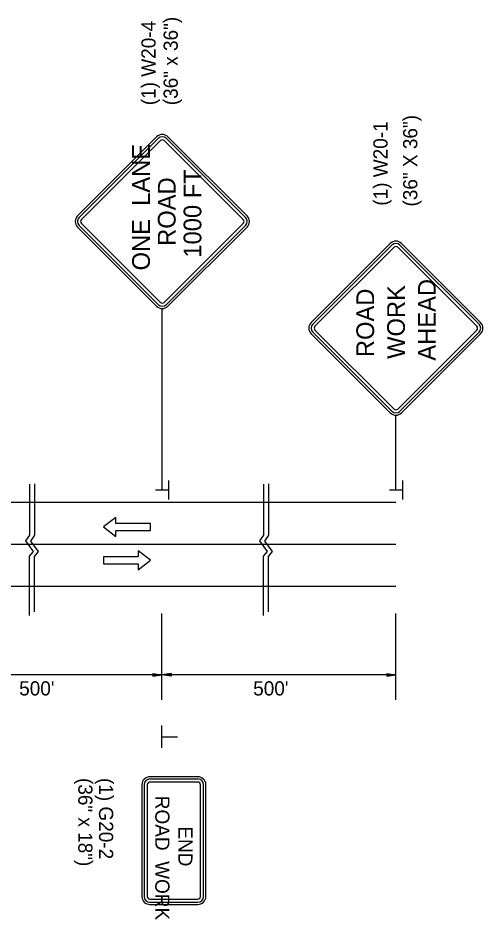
# Model space of a CAD drawing. Extents: x 1926586 to 1930787, y 596452 to 599566.
# Drawn here: x 1928179.6 to 1928376.1, y 598779.1 to 599160.5 of the extents above; entities that cross this region are included whole.
import ezdxf

# ---------------------------------------------------------------- set-up
doc = ezdxf.new("R2010")
doc.units = 0
for name, color, linetype in [('Default', 7, 'Continuous'), ('P_TC_Signs_Temporary', 7, 'Continuous'), ('R_Border', 7, 'Continuous'), ('R_Striping', 7, 'Continuous')]:
    doc.layers.add(name, color=color, linetype=linetype)

msp = doc.modelspace()

# ---------------------------------------------------------------- linework, layer by layer
at = {"layer": 'Default'}
for p, q in [((1928243.29, 598964.87), (1928243.29, 598956.86)), ((1928342.19, 598964.87), (1928342.19, 598956.86)), ((1928243.18, 598960.89), (1928237.71, 598960.89)), ((1928342.08, 598960.89), (1928336.61, 598960.89)), ((1927909.48, 598955.79), (1928339.34, 598955.76)), ((1927909.48, 598938), (1928339.34, 598937.97)), ((1927909.48, 598920.21), (1928339.34, 598920.18)), ((1928240.44, 598872.15), (1928240.44, 598908.73)), ((1928339.34, 598872.15), (1928339.34, 598908.73)), ((1928240.44, 598882.74), (1928140.69, 598882.74)), ((1928236.61, 598883.31), (1928240.44, 598882.74)), ((1928236.61, 598883.31), (1928236.61, 598882.16)), ((1928236.61, 598883.22), (1928239.8, 598882.74)), ((1928236.61, 598883.12), (1928239.14, 598882.74)), ((1928236.61, 598883.02), (1928238.5, 598882.74)), ((1928236.61, 598882.92), (1928237.85, 598882.74)), ((1928236.61, 598882.83), (1928237.21, 598882.74)), ((1928236.61, 598882.16), (1928240.44, 598882.74)), ((1928236.61, 598882.55), (1928237.85, 598882.74)), ((1928236.61, 598882.35), (1928239.14, 598882.74)), ((1928236.61, 598882.26), (1928239.8, 598882.74)), ((1928236.61, 598882.45), (1928238.5, 598882.74)), ((1928236.61, 598882.65), (1928237.21, 598882.74)), ((1928339.34, 598882.74), (1928239.59, 598882.74)), ((1928244.29, 598883.31), (1928240.46, 598882.74)), ((1928244.29, 598882.16), (1928240.46, 598882.74)), ((1928244.29, 598883.22), (1928241.1, 598882.74)), ((1928244.29, 598882.26), (1928241.1, 598882.74)), ((1928244.29, 598883.12), (1928241.76, 598882.74)), ((1928244.29, 598882.35), (1928241.76, 598882.74)), ((1928244.29, 598883.02), (1928242.4, 598882.74)), ((1928244.29, 598882.45), (1928242.4, 598882.74)), ((1928244.29, 598882.92), (1928243.05, 598882.74)), ((1928244.29, 598882.55), (1928243.05, 598882.74)), ((1928244.29, 598882.83), (1928243.69, 598882.74)), ((1928244.29, 598882.65), (1928243.69, 598882.74)), ((1928244.29, 598883.31), (1928244.29, 598882.16)), ((1928335.51, 598883.31), (1928339.34, 598882.74)), ((1928335.51, 598883.31), (1928335.51, 598882.16)), ((1928335.51, 598883.22), (1928338.7, 598882.74)), ((1928335.51, 598883.12), (1928338.04, 598882.74)), ((1928335.51, 598883.02), (1928337.4, 598882.74)), ((1928335.51, 598882.92), (1928336.75, 598882.74)), ((1928335.51, 598882.83), (1928336.11, 598882.74)), ((1928335.51, 598882.16), (1928339.34, 598882.74)), ((1928335.51, 598882.55), (1928336.75, 598882.74)), ((1928335.51, 598882.35), (1928338.04, 598882.74)), ((1928335.51, 598882.26), (1928338.7, 598882.74)), ((1928335.51, 598882.45), (1928337.4, 598882.74)), ((1928335.51, 598882.65), (1928336.11, 598882.74)), ((1928240.44, 598851.83), (1928240.44, 598861.32)), ((1928240.58, 598856.55), (1928247.06, 598856.55))]:
    msp.add_line(p, q, dxfattribs=at)
for points in [[(1928184.51, 598963.37), (1928184.51, 598941.85), (1928182.85, 598939.38), (1928186.09, 598934.95), (1928184.39, 598932.9), (1928184.38, 598907.87)], [(1928186.56, 598963.57), (1928186.56, 598941.76), (1928184.9, 598939.29), (1928188.13, 598934.86), (1928186.43, 598932.81), (1928186.43, 598909.31)], [(1928283.41, 598963.37), (1928283.41, 598941.85), (1928281.75, 598939.38), (1928284.99, 598934.95), (1928283.29, 598932.9), (1928283.28, 598907.87)], [(1928285.46, 598963.57), (1928285.46, 598941.76), (1928283.8, 598939.29), (1928287.03, 598934.86), (1928285.33, 598932.81), (1928285.33, 598909.31)]]:
    msp.add_lwpolyline(points, dxfattribs=at)
at = {"layer": 'P_TC_Signs_Temporary'}
for p, q in [((1928204.82, 599076.83), (1928238.23, 599110.24)), ((1928205.48, 599076.17), (1928238.89, 599109.58)), ((1928242.34, 599109.58), (1928275.75, 599076.17)), ((1928243, 599110.24), (1928276.41, 599076.83)), ((1928206.41, 599075.24), (1928239.82, 599108.65)), ((1928241.41, 599108.65), (1928274.82, 599075.24)), ((1928238.23, 599038.65), (1928204.82, 599072.06)), ((1928238.89, 599039.31), (1928205.48, 599072.72)), ((1928239.82, 599040.24), (1928206.41, 599073.65)), ((1928274.82, 599073.65), (1928241.41, 599040.24)), ((1928275.75, 599072.72), (1928242.34, 599039.31)), ((1928276.41, 599072.06), (1928243, 599038.65)), ((1928303.55, 599031.72), (1928336.96, 599065.13)), ((1928304.21, 599031.05), (1928337.62, 599064.47)), ((1928305.14, 599030.13), (1928338.55, 599063.54)), ((1928340.14, 599063.54), (1928373.55, 599030.13)), ((1928341.07, 599064.47), (1928374.48, 599031.05)), ((1928341.73, 599065.13), (1928375.14, 599031.72)), ((1928336.96, 598993.53), (1928303.55, 599026.94)), ((1928337.62, 598994.2), (1928304.21, 599027.61)), ((1928338.55, 598995.12), (1928305.14, 599028.54)), ((1928373.55, 599028.54), (1928340.14, 598995.12)), ((1928374.48, 599027.61), (1928341.07, 598994.2)), ((1928375.14, 599026.94), (1928341.73, 598993.53)), ((1928255.64, 598839.63), (1928235.39, 598839.63)), ((1928255.64, 598838.69), (1928235.39, 598838.69)), ((1928232.01, 598836.26), (1928232.01, 598789.01)), ((1928232.95, 598836.26), (1928232.95, 598789.01)), ((1928234.26, 598836.26), (1928234.26, 598789.01)), ((1928255.64, 598837.38), (1928235.39, 598837.38)), ((1928256.76, 598789.01), (1928256.76, 598836.26)), ((1928258.08, 598789.01), (1928258.08, 598836.26)), ((1928259.01, 598789.01), (1928259.01, 598836.26)), ((1928235.39, 598787.88), (1928255.64, 598787.88)), ((1928235.39, 598786.57), (1928255.64, 598786.57)), ((1928235.39, 598785.63), (1928255.64, 598785.63))]:
    msp.add_line(p, q, dxfattribs=at)
for centre, radius, start, end in [((1928240.62, 599107.85), 3.38, 45, 135), ((1928240.62, 599107.85), 2.44, 45, 135), ((1928240.62, 599107.85), 1.13, 45, 135), ((1928207.21, 599074.44), 3.38, 135, 225), ((1928207.21, 599074.44), 2.44, 135, 225), ((1928207.21, 599074.44), 1.13, 135, 225), ((1928274.03, 599074.44), 1.13, 315, 45), ((1928274.03, 599074.44), 2.44, 315, 45), ((1928274.03, 599074.44), 3.38, 315, 45), ((1928339.34, 599062.74), 3.38, 45, 135), ((1928339.34, 599062.74), 2.44, 45, 135), ((1928339.34, 599062.74), 1.13, 45, 135), ((1928240.62, 599041.03), 3.38, 225, 315), ((1928240.62, 599041.03), 2.44, 225, 315), ((1928240.62, 599041.03), 1.13, 225, 315), ((1928305.93, 599029.33), 3.38, 135, 225), ((1928305.93, 599029.33), 2.44, 135, 225), ((1928305.93, 599029.33), 1.13, 135, 225), ((1928372.75, 599029.33), 1.13, 315, 45), ((1928372.75, 599029.33), 2.44, 315, 45), ((1928372.75, 599029.33), 3.38, 315, 45), ((1928339.34, 598995.92), 1.13, 225, 315), ((1928339.34, 598995.92), 3.38, 225, 315), ((1928339.34, 598995.92), 2.44, 225, 315), ((1928235.39, 598836.26), 3.37, 90, 180), ((1928235.39, 598836.26), 2.44, 90, 180), ((1928255.64, 598836.26), 3.37, 360, 90), ((1928255.64, 598836.26), 2.44, 360, 90), ((1928235.39, 598836.26), 1.13, 90, 180), ((1928255.64, 598836.26), 1.13, 360, 90), ((1928235.39, 598789.01), 3.37, 180, 270), ((1928235.39, 598789.01), 2.44, 180, 270), ((1928235.39, 598789.01), 1.13, 180, 270), ((1928255.64, 598789.01), 2.44, 270, 360), ((1928255.64, 598789.01), 1.13, 270, 360), ((1928255.64, 598789.01), 3.37, 270, 360)]:
    msp.add_arc(centre, radius, start, end, dxfattribs=at)
at = {"layer": 'R_Border'}
for p, q in [((1928240.62, 598960.89), (1928240.62, 599037.66)), ((1928339.34, 598960.89), (1928339.34, 598992.54))]:
    msp.add_line(p, q, dxfattribs=at)
at = {"layer": 'R_Striping'}
for points in [[(1928220.95, 598949.3), (1928215.76, 598945.3), (1928220.95, 598941.3), (1928220.95, 598943.8), (1928235.67, 598943.8), (1928235.67, 598946.8), (1928220.95, 598946.8)], [(1928230.47, 598927.16), (1928235.67, 598931.16), (1928230.47, 598935.16), (1928230.47, 598932.66), (1928215.76, 598932.66), (1928215.76, 598929.66), (1928230.47, 598929.66)]]:
    msp.add_lwpolyline(points, close=True, dxfattribs=at)

# ---------------------------------------------------------------- texts
at = {"layer": 'Default'}
for s, rotation, p in [('(36" X 36")', 90, (1928348.39, 599080.78)), ('(1) W20-1', 90, (1928335.81, 599081.12)), ("500'", 359.9922, (1928180.12, 598874.01)), ("500'", 359.9922, (1928279.02, 598874.01))]:
    msp.add_text(s, height=6, rotation=rotation, dxfattribs=at).set_placement(p)
at = {"layer": 'P_TC_Signs_Temporary'}
for s, height, rotation, p in [('ONE  LANE', 7.5, 90, (1928235.37, 599053.74)), ('1000 FT', 7.5, 90, (1928257.12, 599059.15)), ('ROAD', 7.5, 90, (1928246.24, 599064.14)), (' AHEAD ', 7.5, 90, (1928356.18, 599012.79)), (' ROAD ', 7.5, 90, (1928330.13, 599014.31)), ('WORK', 7.5, 90, (1928343.15, 599016.34)), ('ROAD  WORK', 6, 270, (1928237.64, 598831.59)), ('END', 6, 270, (1928247.39, 598818.66))]:
    msp.add_text(s, height=height, rotation=rotation, dxfattribs=at).set_placement(p)
at = {"layer": 'R_Border'}
for s, height, rotation, p in [('(1) W20-4', 6, 90, (1928237.79, 599123.62)), ('(36" x 36")', 5.9996, 90, (1928247.15, 599123.62)), ('(36" x 18")', 5.9996, 270, (1928205.11, 598839.12)), ('(1) G20-2', 6, 270, (1928213.86, 598839.12))]:
    msp.add_text(s, height=height, rotation=rotation, dxfattribs=at).set_placement(p)

doc.saveas('drawing.dxf')
